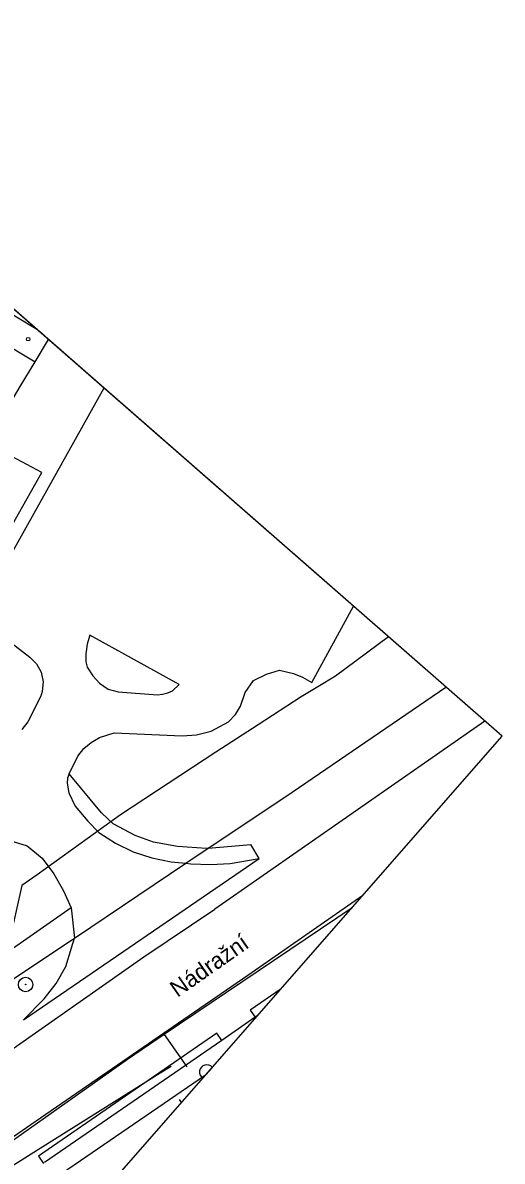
# Model space of a CAD drawing. Extents: x -620475 to -619963, y -1123010 to -1122510.
# Drawn here: x -620012.5 to -619962.9, y -1122830.6 to -1122712.8 of the extents above; entities that cross this region are included whole.
import ezdxf

# ---------------------------------------------------------------- set-up
doc = ezdxf.new("R2010")
doc.units = 0
for name, color, linetype in [('GasNet', 7, 'Continuous'), ('Hranice parcel', 7, 'Continuous'), ('Pop  PČ popisy', 7, 'Continuous'), ('Rámečky', 7, 'Continuous'), ('Rámečky-tisk', 7, 'Continuous'), ('VAS stoka', 7, 'Continuous'), ('VAS vodovod', 7, 'Continuous'), ('Vnitřní kresba', 7, 'Continuous'), ('Věcná břemena k části', 7, 'Continuous'), ('Značky bodu BP', 7, 'Continuous'), ('Značky budov', 7, 'Continuous'), ('Značky kultur', 7, 'Continuous')]:
    doc.layers.add(name, color=color, linetype=linetype)

msp = doc.modelspace()

# ---------------------------------------------------------------- linework, layer by layer
at = {"layer": 'GasNet'}
for points in [[(-619978.45, -1122804.33), (-619997.91, -1122817.46), (-620001.69, -1122820.05), (-620016.67, -1122830.62), (-620025.79, -1122837.14), (-620030.05, -1122839.94), (-620046.14, -1122851.29)], [(-619997.91, -1122817.46), (-619995.56, -1122820.8)]]:
    msp.add_lwpolyline(points, dxfattribs=at)
at = {"layer": 'Hranice parcel'}
for p, q in [((-620014.82, -1122742.21), (-620011.18, -1122744.41)), ((-620016.36, -1122744.78), (-620011.23, -1122747.87)), ((-620011.23, -1122747.87), (-620009.85, -1122745.57)), ((-620012.77, -1122750.41), (-620011.23, -1122747.87)), ((-620007.52, -1122804.34), (-620007.17, -1122807.47))]:
    msp.add_line(p, q, dxfattribs=at)
for points in [[(-620004.12, -1122750.58), (-620017.33, -1122774.17), (-620018.54, -1122773.42)], [(-620015.21, -1122767.58), (-620013.28, -1122764.14), (-620010.56, -1122759.32), (-620016.25, -1122756.27), (-620012.77, -1122750.41)], [(-619993.34, -1122798.19), (-619993.51, -1122798.21), (-619996.52, -1122797.99), (-619999.01, -1122797.54), (-620000.91, -1122796.86), (-620003.16, -1122795.65), (-620004.39, -1122794.52), (-620007.71, -1122790.48), (-620006.81, -1122788.65), (-620006.19, -1122787.87), (-620005.43, -1122787.26), (-620004.57, -1122786.74), (-620003.06, -1122786.26), (-619996.05, -1122786.56), (-619994.54, -1122786.44), (-619993.04, -1122786.08), (-619991.26, -1122785.1), (-619990.52, -1122784.36), (-619990, -1122783.48), (-619989.53, -1122782.06), (-619988.65, -1122780.83), (-619987.32, -1122780.16), (-619985.99, -1122779.75), (-619984.54, -1122780.1), (-619983.61, -1122780.49), (-619982.64, -1122781.05), (-619978.32, -1122773.15)], [(-619993.34, -1122798.19), (-619985.33, -1122792.82), (-619968.77, -1122781.51)], [(-620013.97, -1122797.33), (-620012.05, -1122797.95), (-620010.5, -1122799.22), (-620009.31, -1122800.82), (-620008.3, -1122802.58), (-620007.52, -1122804.34)], [(-620007.17, -1122807.47), (-619995.65, -1122799.74), (-619993.34, -1122798.19)], [(-619977.35, -1122803.07), (-619989.26, -1122811.36), (-619995.85, -1122815.89), (-620011.68, -1122826.8), (-620019.22, -1122832.01), (-620044.54, -1122849.47), (-620064.79, -1122863.44), (-620079.86, -1122873.87), (-620081.95, -1122879.05), (-620081.71, -1122879.39)], [(-620007.52, -1122804.34), (-620014.61, -1122809.32), (-620021.11, -1122813.89), (-620023.96, -1122816.62), (-620025.58, -1122819.12), (-620026.52, -1122820.79)], [(-620021.18, -1122817.07), (-620013.01, -1122811.39), (-620007.39, -1122807.62), (-620007.17, -1122807.47)], [(-619988.22, -1122815.49), (-619988.48, -1122815.67), (-619991.93, -1122818.06), (-620010.26, -1122830.7)]]:
    msp.add_lwpolyline(points, dxfattribs=at)
at = {"layer": 'Rámečky'}
for p, q in [((-619962.95, -1122786.6), (-620279.07, -1122510.07)), ((-620158.49, -1123010.14), (-619962.95, -1122786.6))]:
    msp.add_line(p, q, dxfattribs=at)
at = {"layer": 'Rámečky-tisk'}
msp.add_lwpolyline([(-620158.49, -1123010.14), (-619962.95, -1122786.6), (-620279.07, -1122510.07)], dxfattribs=at)
at = {"layer": 'VAS stoka'}
msp.add_lwpolyline([(-619997.17, -1122820.75), (-619998.31, -1122821.46), (-620010.73, -1122829.25), (-620019.05, -1122834.47)], dxfattribs=at)
at = {"layer": 'VAS vodovod'}
msp.add_line((-619996.1, -1122824.5), (-619996.32, -1122824.17), dxfattribs=at)
for points in [[(-619974.71, -1122776.31), (-619980.2, -1122780.38), (-619982.02, -1122781.49), (-619983.73, -1122782.53), (-619988.19, -1122785.41), (-619992.55, -1122788.24), (-619997.47, -1122791.49), (-620002.4, -1122794.74), (-620006.71, -1122797.84), (-620011.04, -1122800.95), (-620011.83, -1122801.49), (-620012.62, -1122802.02), (-620013.19, -1122804.65), (-620013.77, -1122807.28), (-620018.79, -1122810.81), (-620023.82, -1122814.35), (-620035.32, -1122822.27), (-620046.82, -1122830.19), (-620050.81, -1122832.92), (-620054.81, -1122835.64), (-620056.56, -1122836.89), (-620058.31, -1122838.14), (-620058.56, -1122838.3), (-620058.81, -1122838.46)], [(-619993.63, -1122821.67), (-620009.07, -1122832.23), (-620021.42, -1122839.54), (-620042.52, -1122853.63), (-620044.71, -1122856.33)]]:
    msp.add_lwpolyline(points, dxfattribs=at)
at = {"layer": 'Vnitřní kresba'}
for p, q in [((-620017.33, -1122774.17), (-620011.79, -1122778.42)), ((-620005.57, -1122776.13), (-620005.85, -1122777.08)), ((-619996.33, -1122781.23), (-620005.57, -1122776.13)), ((-620005.85, -1122777.08), (-620006.01, -1122778.08)), ((-620011.79, -1122778.42), (-620011.09, -1122779.1)), ((-620011.09, -1122779.1), (-620010.6, -1122779.97)), ((-620006.01, -1122778.08), (-620005.98, -1122778.9)), ((-620005.98, -1122778.9), (-620005.86, -1122779.45)), ((-620010.6, -1122779.97), (-620010.42, -1122780.98)), ((-620005.86, -1122779.45), (-620005.28, -1122780.34)), ((-620010.42, -1122780.98), (-620010.5, -1122781.96)), ((-620005.28, -1122780.34), (-620004.59, -1122781.12)), ((-620004.59, -1122781.12), (-620003.7, -1122781.74)), ((-619997.02, -1122781.9), (-619996.33, -1122781.23)), ((-620010.64, -1122782.44), (-620011.99, -1122785.12)), ((-620010.5, -1122781.96), (-620010.64, -1122782.44)), ((-620003.7, -1122781.74), (-620002.66, -1122782)), ((-620002.66, -1122782), (-619998.58, -1122782.3)), ((-619998.58, -1122782.3), (-619998.07, -1122782.26)), ((-619998.07, -1122782.26), (-619997.52, -1122782.12)), ((-619997.52, -1122782.12), (-619997.02, -1122781.9)), ((-620011.99, -1122785.12), (-620012.63, -1122785.89)), ((-619964.74, -1122785.03), (-619992.67, -1122804.48)), ((-620007.71, -1122790.48), (-620007.9, -1122790.93)), ((-620007.9, -1122790.93), (-620007.92, -1122791.46)), ((-620007.92, -1122791.46), (-620007.77, -1122792.46)), ((-620007.77, -1122792.46), (-620007.09, -1122793.84)), ((-620007.09, -1122793.84), (-620005.78, -1122795.39)), ((-620005.78, -1122795.39), (-620004.64, -1122796.54)), ((-620004.64, -1122796.54), (-620002.93, -1122797.66)), ((-620002.93, -1122797.66), (-620001.11, -1122798.55)), ((-619993.34, -1122798.19), (-619988.95, -1122797.79)), ((-619988.07, -1122799.25), (-619988.95, -1122797.79)), ((-620001.11, -1122798.55), (-619999.17, -1122799.18)), ((-620012.45, -1122815.92), (-619988.07, -1122799.25)), ((-619999.17, -1122799.18), (-619997.16, -1122799.6)), ((-619997.16, -1122799.6), (-619995.65, -1122799.74)), ((-619995.65, -1122799.74), (-619995.15, -1122799.79)), ((-619995.15, -1122799.79), (-619993.12, -1122799.86)), ((-619993.12, -1122799.86), (-619991.09, -1122799.77)), ((-619991.09, -1122799.77), (-619988.07, -1122799.25)), ((-620000, -1122809.41), (-619992.67, -1122804.48)), ((-620008.06, -1122810.42), (-620007.48, -1122808.49)), ((-620007.48, -1122808.49), (-620007.17, -1122807.47)), ((-620030.04, -1122830.5), (-620000, -1122809.41)), ((-620009.06, -1122812.19), (-620008.06, -1122810.42)), ((-620010.31, -1122813.76), (-620009.06, -1122812.19)), ((-619985.8, -1122812.72), (-619988.99, -1122814.93)), ((-620012.45, -1122815.92), (-620010.31, -1122813.76)), ((-619988.99, -1122814.93), (-619988.48, -1122815.67)), ((-619992.45, -1122817.31), (-620010.9, -1122830.03)), ((-619991.93, -1122818.06), (-619992.45, -1122817.31)), ((-620010.9, -1122830.03), (-620010.39, -1122830.79))]:
    msp.add_line(p, q, dxfattribs=at)
at = {"layer": 'Věcná břemena k části'}
msp.add_lwpolyline([(-620013.28, -1122764.14), (-620010.56, -1122759.32), (-620016.25, -1122756.27)], dxfattribs=at)
msp.add_lwpolyline([(-620013.28, -1122764.14), (-620010.56, -1122759.32), (-620016.25, -1122756.27)], dxfattribs=at)
msp.add_lwpolyline([(-620013.28, -1122764.14), (-620010.56, -1122759.32), (-620016.25, -1122756.27)], dxfattribs=at)
msp.add_lwpolyline([(-620013.28, -1122764.14), (-620010.56, -1122759.32), (-620016.25, -1122756.27)], dxfattribs=at)
at = {"layer": 'Značky bodu BP'}
for radius in [0.75, 0.03]:
    msp.add_circle((-620012.22, -1122812.28), radius, dxfattribs=at)
at = {"layer": 'Značky budov'}
msp.add_circle((-620011.96, -1122745.52), 0.175, dxfattribs=at)
at = {"layer": 'Značky kultur'}
msp.add_line((-619993.89, -1122821.97), (-619992.91, -1122820.86), dxfattribs=at)
msp.add_arc((-619993.49, -1122821.33), 0.75, 39.2648, 238.3794, dxfattribs=at)

# ---------------------------------------------------------------- texts
at = {"layer": 'Pop  PČ popisy'}
msp.add_text('Nádražní', height=1.7, rotation=35, dxfattribs=at).set_placement((-619996.53, -1122813.66))

doc.saveas('drawing.dxf')
